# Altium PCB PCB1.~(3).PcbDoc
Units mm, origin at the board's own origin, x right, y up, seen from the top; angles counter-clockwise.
Board outline 48.89 x 49.4 mm, 2 copper layers (Top Layer, Bottom Layer); 29 components, 26 nets, 101 pads, 0 vias.
Unrouted connection lines stored in the file: 55.
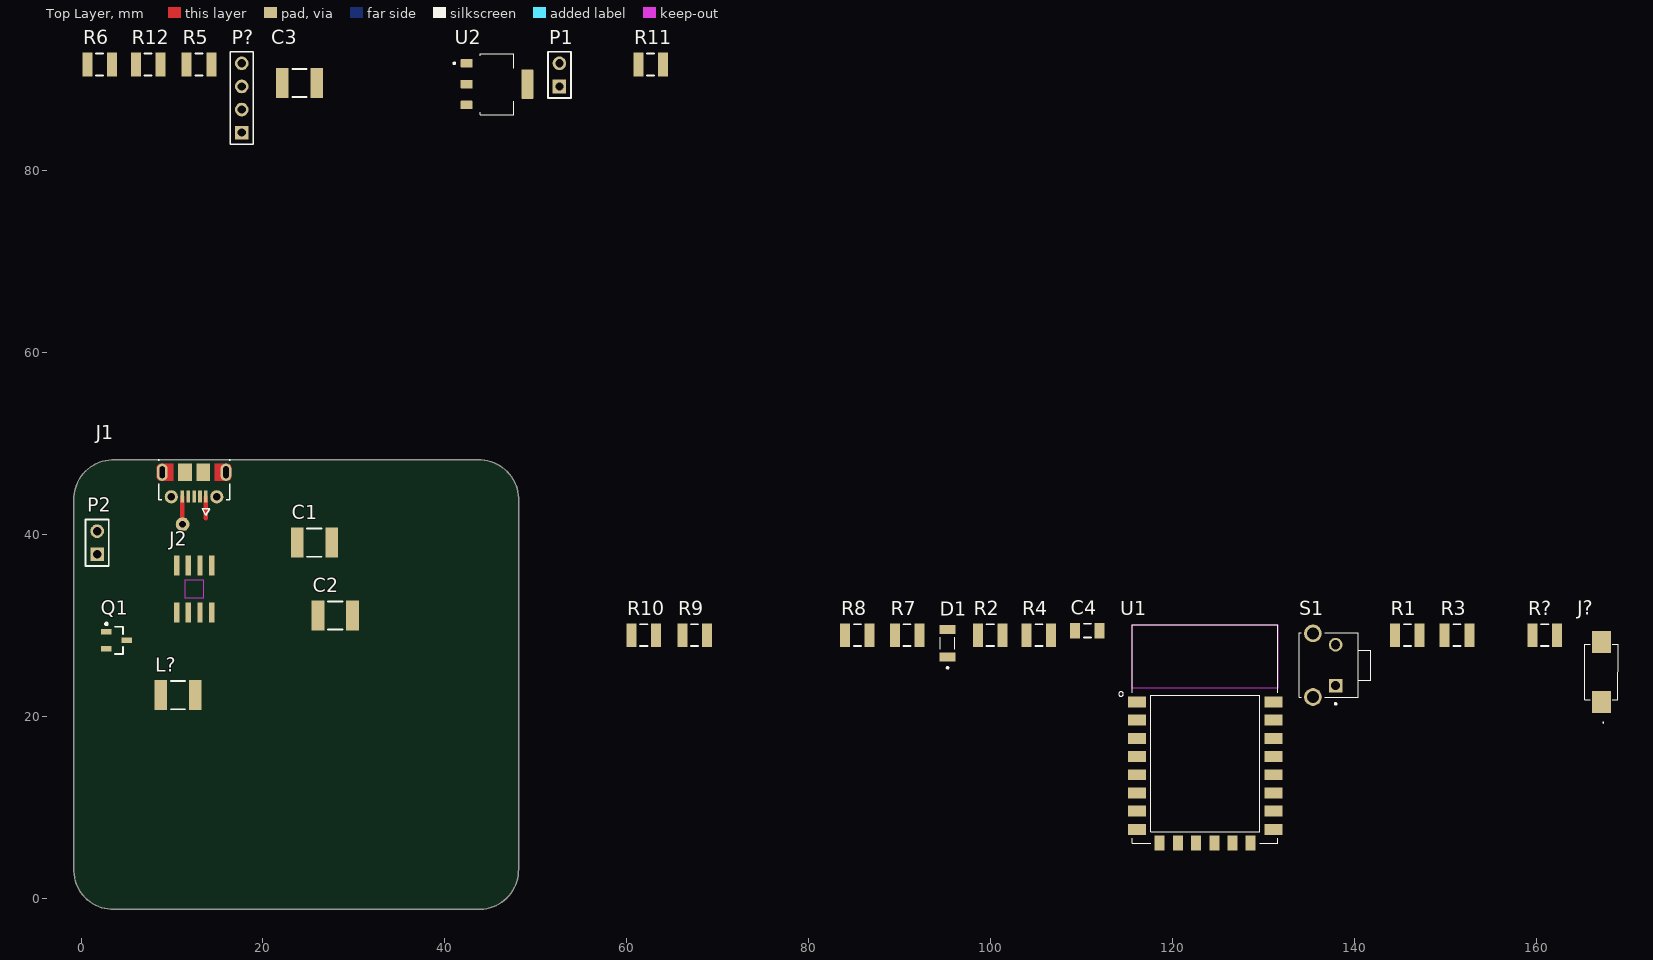
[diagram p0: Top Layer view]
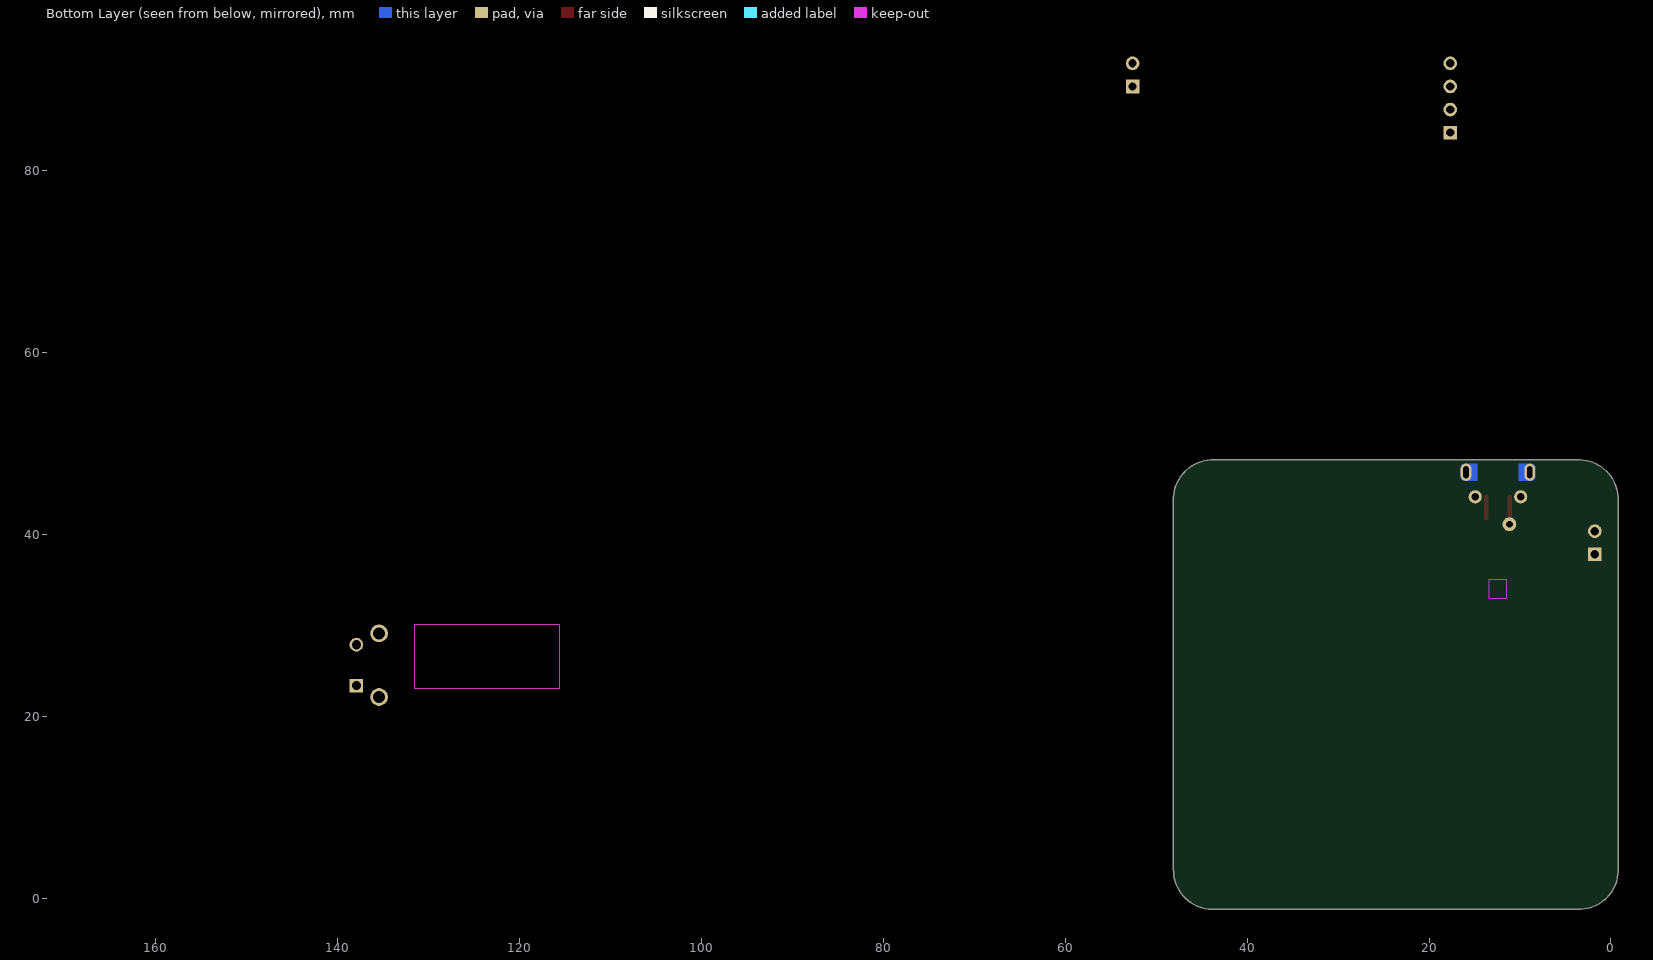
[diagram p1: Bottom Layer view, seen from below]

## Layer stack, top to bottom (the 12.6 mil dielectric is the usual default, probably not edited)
Top Solder: solder mask 0.0102, Solder Resist, Dk 3.5
Top Layer: signal copper 0.0356
Dielectric 1: dielectric 0.32, FR-4, Dk 4.8
Bottom Layer: signal copper 0.0356
Bottom Solder: solder mask 0.0102, Solder Resist, Dk 3.5

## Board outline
-0.794,3.006 -0.794,43.773 cw(c3.524,43.9) 3.397,48.218 43.656,48.218 cw(c43.783,43.9) 48.101,44.027 48.101,3.26 cw(c43.783,3.133) 43.91,-1.185 3.651,-1.185 cw(c3.524,3.133)

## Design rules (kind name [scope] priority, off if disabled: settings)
Clearance [All] p1: gap=0.254 ignorepadtopadclearanceinfootprint=FALSE except(0: Arc-Hole Track-Hole SMDPad-Hole THPad-Hole Via-Hole Fill-Hole Poly-Hole Region-Hole Text-Hole)
PolygonConnect [All] p1: connectstyle=Relief reliefconductorwidth=0.254 reliefentries=4 polygonreliefangle="90 Angle" airgapwidth=0.254
RoomDefinition Sheet1 [InComponentClass('Sheet1')] p1: confinementstyle=ConfineIn formatcopy=TRUE lockcomponents=FALSE outline 154.781,-50.588 347.313,-50.588 347.313,-19.854 154.781,-19.854
RoutingVias [All] p1: holewidth=0.711 width=1.27 viastyle="Through Hole" minholewidth=0.711 minwidth=1.27 maxholewidth=0.711 maxwidth=1.27
SolderMaskExpansion [All] p1: expansion=0.102 istentingtop=FALSE
Width [All] p1: maxlimit=1 minlimit=1 preferedwidth=1 minimp=50.000000 maximp=50.000000 favimp=50.000000
30 further rules are at their usual default settings.

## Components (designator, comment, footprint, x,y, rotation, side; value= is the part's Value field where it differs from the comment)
C1 "" 1812 25.659,39.116 r0 top value=10uF
C2 "" 1812 27.945,31.115 r0 top value=10uF
C3 "" 1812 24.021,89.662 r0 top value=10uF
C4 "" C1206 110.635,29.464 r0 top value=100pF
D1 "LED" LEDC3216X120N 95.268,28.067 r90 top
J1 "1050170001" MOLEX_1050170001 12.43,48.313 r180 top
J2 "L9110" SO-08 12.446,34.036 r0 top
J? "SWITCH" PTS636SM25FSMTRLFS 167.15,24.892 r90 top
L? "Inductor" INDC4532 10.668,22.352 r0 top value=47uH
P1 "Battery" HDR1X2 52.596,89.281 r90 top
P2 "Battery" HDR1X2 1.778,37.846 r90 top
P? "Header 4" HDR1X4 17.671,84.201 r90 top
Q1 "PNP" SOT-23B_N 3.919,28.387 r0 top
R1 "" 14-1210 145.814,28.956 r0 top value=1K
R2 "" 14-1210 99.967,28.956 r0 top value=1K
R3 "" 14-1210 151.275,28.956 r0 top value=1K
R4 "" 14-1210 105.301,28.956 r0 top value=1K
R5 "" 14-1210 12.972,91.694 r0 top value=1K
R6 "" 14-1210 2.05,91.694 r0 top value=1K
R7 "" 14-1210 90.823,28.956 r0 top value=1K
R8 "" 14-1210 85.362,28.956 r0 top value=1K
R9 "" 14-1210 67.455,28.956 r0 top value=1K
R10 "" 14-1210 61.867,28.956 r0 top value=1K
R11 "" 14-1210 62.629,91.694 r0 top value=1K
R12 "" 14-1210 7.384,91.694 r0 top value=1K
R? "" 14-1210 160.927,28.956 r0 top value=1K
S1 "TL1105VF160Q" SW_TL1105VF160Q 137.94,25.654 r90 top
U1 "ESP8266-12E/ESP-12E" XCVR_ESP8266-12E/ESP-12E 123.589,14.605 r0 top
U2 "AMS1117" SOT229P700X180-4N 45.738,89.535 r0 top

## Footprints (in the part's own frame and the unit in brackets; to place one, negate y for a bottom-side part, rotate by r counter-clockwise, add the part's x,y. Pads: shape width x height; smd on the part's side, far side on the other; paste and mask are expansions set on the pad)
14-1210 [mm] "Chip Resistor, Body 3.2x2.5mm, IPC High Density"
  rect 1.1x2.6 smd: 1(-1.35,0) 2(1.35,0)
  silkscreen extent -0.4,-1.2 0.4,1.2, body extent -1.68,-1.32 1.68,1.32, height 0.9
1812 [mm] "Chip Capacitor, Body 4.5x3.2mm, IPC High Density"
  rect 1.4x3.3 smd: 1(-1.9,0) 2(1.9,0)
  silkscreen extent -0.8,-1.55 0.8,1.55, body extent -2.4,-1.7 2.4,1.7, height 1.4
C1206 [mm] "Chip Capacitor, Body 3.2x1.6mm, IPC High Density"
  rect 1.1x1.7 smd: 1(-1.35,0) 2(1.35,0)
  silkscreen extent -0.4,-0.75 0.4,0.75, body extent -1.7,-0.9 1.7,0.9, height 1.3
HDR1X2 [mm] "Connector; Header; 2 Position"
  rect 1.5x1.5 hole 0.9: 1(0,0)
  round 1.5 hole 0.9: 2(2.54,0)
  silkscreen extent -1.27,-1.27 3.81,1.27
HDR1X4 [mm] "Connector; Header; 4 Position"
  rect 1.5x1.5 hole 0.9: 1(0,0)
  round 1.5 hole 0.9: 2(2.54,0) 3(5.08,0) 4(7.62,0)
  silkscreen extent -1.27,-1.27 8.89,1.27
INDC4532 [mm] "Chip Inductor, Body 4.5x3.2mm, IPC High Density"
  rect 1.4x3.3 smd: 1(-1.9,0) 2(1.9,0)
  silkscreen extent -0.8,-1.55 0.8,1.55, body extent -2.4,-1.7 2.4,1.7, height 0.55
LEDC3216X120N [mm]
  rect 1.01x1.73 smd: NEG(1.51,0) POS(-1.51,0)
  silkscreen extent -2.8,-0.8 0.68,0.8, body extent -1.6,-0.8 1.6,0.8, height 1.2
MOLEX_1050170001 [mm]
  rect 0.4x1.35 smd mask+0.064: 1(-1.3,4.125) 2(-0.65,4.125) 3(0,4.125) 4(0.65,4.125) 5(1.3,4.125)
  round 1.45 hole 0.85 mask+0.064: SH1(-2.5,4.15) SH2(2.5,4.15)
  oval 1.2x1.9 hole 0.6 slot 1.3 at 90 deg mask+0: SH3(-3.5,1.45) SH6(3.5,1.45)
  rect 1.5x1.9 smd mask+0.064: SH4(-1,1.45) SH5(1,1.45)
  Top Layer region: -2.3,0.5 -3.6,0.5 -3.626,0.501 -3.652,0.503 -3.678,0.506 -3.704,0.511 -3.729,0.517 -3.755,0.524 -3.779,0.533 -3.803,0.543 -3.827,0.554 -3.85,0.567 -3.872,0.581 -3.894,0.595 -3.915,0.611 -3.935,0.628 -3.954,0.646 -3.972,0.665 -3.989,0.685 -4.005,0.706 -4.019,0.728 -4.033,0.75 -4.046,0.773 -4.057,0.797 -4.067,0.821 -4.076,0.845 -4.083,0.871 -4.089,0.896 -4.094,0.922 -4.097,0.948 -4.099,0.974 -4.1,1 -4.1,1.9 -4.099,1.926 -4.097,1.952 -4.094,1.978 -4.089,2.004 -4.083,2.029 -4.076,2.055 -4.067,2.079 -4.057,2.103 -4.046,2.127 -4.033,2.15 -4.019,2.172 -4.005,2.194 -3.989,2.215 -3.972,2.235 -3.954,2.254 -3.935,2.272 -3.915,2.289 -3.894,2.305 -3.872,2.319 -3.85,2.333 -3.827,2.346 -3.803,2.357 -3.779,2.367 -3.755,2.376 -3.729,2.383 -3.704,2.389 -3.678,2.394 -3.652,2.397 -3.626,2.399 -3.6,2.4 -2.3,2.4
  Top Layer region: 3.626,2.399 3.652,2.397 3.678,2.394 3.704,2.389 3.729,2.383 3.755,2.376 3.779,2.367 3.803,2.357 3.827,2.346 3.85,2.333 3.872,2.319 3.894,2.305 3.915,2.289 3.935,2.272 3.954,2.254 3.972,2.235 3.989,2.215 4.005,2.194 4.019,2.172 4.033,2.15 4.046,2.127 4.057,2.103 4.067,2.079 4.076,2.055 4.083,2.029 4.089,2.004 4.094,1.978 4.097,1.952 4.099,1.926 4.1,1.9 4.1,1 4.099,0.974 4.097,0.948 4.094,0.922 4.089,0.896 4.083,0.871 4.076,0.845 4.067,0.821 4.057,0.797 4.046,0.773 4.033,0.75 4.019,0.728 4.005,0.706 3.989,0.685 3.972,0.665 3.954,0.646 3.935,0.628 3.915,0.611 3.894,0.595 3.872,0.581 3.85,0.567 3.827,0.554 3.803,0.543 3.779,0.533 3.755,0.524 3.729,0.517 3.704,0.511 3.678,0.506 3.652,0.503 3.626,0.501 3.6,0.5 2.3,0.5 2.3,2.4 3.6,2.4
  Bottom Layer region: 3.626,2.399 3.652,2.397 3.678,2.394 3.704,2.389 3.729,2.383 3.755,2.376 3.779,2.367 3.803,2.357 3.827,2.346 3.85,2.333 3.872,2.319 3.894,2.305 3.915,2.289 3.935,2.272 3.954,2.254 3.972,2.235 3.989,2.215 4.005,2.194 4.019,2.172 4.033,2.15 4.046,2.127 4.057,2.103 4.067,2.079 4.076,2.055 4.083,2.029 4.089,2.004 4.094,1.978 4.097,1.952 4.099,1.926 4.1,1.9 4.1,1 4.099,0.974 4.097,0.948 4.094,0.922 4.089,0.896 4.083,0.871 4.076,0.845 4.067,0.821 4.057,0.797 4.046,0.773 4.033,0.75 4.019,0.728 4.005,0.706 3.989,0.685 3.972,0.665 3.954,0.646 3.935,0.628 3.915,0.611 3.894,0.595 3.872,0.581 3.85,0.567 3.827,0.554 3.803,0.543 3.779,0.533 3.755,0.524 3.729,0.517 3.704,0.511 3.678,0.506 3.652,0.503 3.626,0.501 3.6,0.5 2.3,0.5 2.3,2.4 3.6,2.4
  Bottom Layer region: -2.3,0.5 -3.6,0.5 -3.626,0.501 -3.652,0.503 -3.678,0.506 -3.704,0.511 -3.729,0.517 -3.755,0.524 -3.779,0.533 -3.803,0.543 -3.827,0.554 -3.85,0.567 -3.872,0.581 -3.894,0.595 -3.915,0.611 -3.935,0.628 -3.954,0.646 -3.972,0.665 -3.989,0.685 -4.005,0.706 -4.019,0.728 -4.033,0.75 -4.046,0.773 -4.057,0.797 -4.067,0.821 -4.076,0.845 -4.083,0.871 -4.089,0.896 -4.094,0.922 -4.097,0.948 -4.099,0.974 -4.1,1 -4.1,1.9 -4.099,1.926 -4.097,1.952 -4.094,1.978 -4.089,2.004 -4.083,2.029 -4.076,2.055 -4.067,2.079 -4.057,2.103 -4.046,2.127 -4.033,2.15 -4.019,2.172 -4.005,2.194 -3.989,2.215 -3.972,2.235 -3.954,2.254 -3.935,2.272 -3.915,2.289 -3.894,2.305 -3.872,2.319 -3.85,2.333 -3.827,2.346 -3.803,2.357 -3.779,2.367 -3.755,2.376 -3.729,2.383 -3.704,2.389 -3.678,2.394 -3.652,2.397 -3.626,2.399 -3.6,2.4 -2.3,2.4
  silkscreen extent -3.9,0 3.9,6.15
PTS636SM25FSMTRLFS [mm]
  rect 2.4x2.1 smd: 1(-3.3,0) 2(3.3,0)
  silkscreen extent -5.6,-1.85 3.05,1.85, body extent -4.29,-2.8 4.29,0, height 1.85
SO-08 [mm]
  rect 0.6x2.2 smd: 1(-1.905,-2.6) 2(-0.635,-2.6) 3(0.635,-2.6) 4(1.905,-2.6) 5(1.905,2.6) 6(0.635,2.6) 7(-0.635,2.6) 8(-1.905,2.6)
  Keep-Out Layer region: 1,-1 -1,-1 -1,1 1,1
SOT229P700X180-4N [mm]
  rrect15% 1.31x0.93 smd: 1(-3.345,2.29) 2(-3.345,0) 3(-3.345,-2.29)
  rrect15% 1.31x3.24 smd: 4(3.345,0)
  silkscreen extent -4.8,-3.36 1.86,3.36, body extent -3.25,-3.5 3.25,3.5, height 1.8
SOT-23B_N [mm] "SOT23, 3-Leads, Body 2.9x1.3mm, Pitch 0.95mm, Lead Span 2.4mm, IPC Medium Density"
  rect 1.15x0.6 smd: 1(-1.125,0.95) 2(-1.125,-0.95) 3(1.125,0)
  silkscreen extent -1.25,-1.5 0.7,1.92, body extent -0.7,-1.5 0.7,1.5, height 1.14
SW_TL1105VF160Q [mm]
  rect 1.508x1.508 / inner round 1.508 / far side rect 1.508x1.508 hole 1 mask+0.102: 1(-2.25,0)
  round 1.508 hole 1 mask+0.102: 2(2.25,0)
  round 1.95 hole 1.3 mask+0.102: S1(-3.5,2.5) S2(3.5,2.5)
  silkscreen extent -4.35,-3.85 3.55,4, body extent -7.7,-4.64 3.3,3.21, height 4.2
XCVR_ESP8266-12E/ESP-12E [mm]
  rect 2x1.2 smd: 1(-7.5,7) 2(-7.5,5) 3(-7.5,3) 4(-7.5,1) 5(-7.5,-1) 6(-7.5,-3) 7(-7.5,-5) 8(-7.5,-7) 15(7.5,-7) 16(7.5,-5) 17(7.5,-3) 18(7.5,-1) 19(7.5,1) 20(7.5,3) 21(7.5,5) 22(7.5,7)
  rect 1.1x1.7 smd: 9(-5,-8.5) 10(-3,-8.5) 11(-1,-8.5) 12(1,-8.5) 13(3,-8.5) 14(5,-8.5)
  Keep-Out Layer region: 8,8.51 -8.009,8.51 -8.009,15.5 8,15.5
  Keep-Out Layer region: 8,8.51 -8.009,8.51 -8.009,15.5 8,15.5
  silkscreen extent -9.5,-8.5 8,15.5, body extent -8,-12 8,12, height 3

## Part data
C1 C2 C3: library part "Cap Pol3", "Polarized Capacitor (Surface Mount)"
C4: library part "Cap Semi", "Capacitor (Semiconductor SIM Model)"
D1: library part LHN974_RED_LED_1206, "2.6 V Red LED SMD", Package=None
J1: "USB - micro B USB 2.0 Receptacle Connector 5 Position Surface Mount, Right Angle; Through Hole", Package=None
J2: "Motor control driver chip", Package=Package
J?: library part PTS636_SM25F_SMTR_LFS, "Tactile Switch SPST-NO Top Actuated Surface Mount", Package=None
P1 P2: library part "Header 2", "Header, 2-Pin"
P?: "Header, 4-Pin"
Q1: "PNP Bipolar Transistor"
R1 R2 R3 R4 R5 R6 R7 R8 R9 R10 R11 R12 R?: library part Res3, "Resistor"
S1: "Tactile Switch, TL1105 Series, SPST-NO, 3.85mm Side Actuated, 0.05A, 12VDC, PC", Package=None
U1: "This WiFi module has a 32-bit MCU micro and clock speeds supporting 80 MHz or 160 MHz. Supports the RTOS and integrated Wi-Fi MAC/BB/RF/PA/LNA, and has an on-board antenna.", Package=None
U2: "1A LOW DROPOUT VOLTAGE REGULATOR SOT-223", Package="SOT-223 Seeed Technology"

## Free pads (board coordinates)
  round 1.524 hole 0.762: 2(11.176,41.148)

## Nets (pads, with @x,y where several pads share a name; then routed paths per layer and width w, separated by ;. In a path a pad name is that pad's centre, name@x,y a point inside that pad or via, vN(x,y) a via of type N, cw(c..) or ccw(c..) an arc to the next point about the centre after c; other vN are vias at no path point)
+3.3: C3.1 P?.4 R9.2 R10.2 R11.2 R12.1 S1.1 U1.8 U2.2 U2.4
+5: J1.1 U2.3 | length 2.4
  Top Layer w0.5: 13.73,41.797 J1.1
ADC: R3.1 R4.1 U1.2
Battery: P2.1 Q1.3 R4.2
EN: R9.1 U1.3
GND: C1.2 C2.2 C3.2 C4.1 D1.NEG J1.5 J2.7 J2.8 J?.2 P2.2 P?.1 pad.2 R3.2 R8.2 U1.15 U2.1 | length 2.2
  Top Layer w0.5: 11.13,41.956 J1.5
GPIO0: R11.1 U1.18
GPIO2: R10.1 U1.17
GPIO4: R7.1 U1.19
GPIO5: R2.2 U1.20
GPIO13: P?.3 R12.2 U1.7
GPIO14: R5.2 U1.5
GPIO15: R8.1 U1.16
GPIO16: R6.2 U1.4
L1: J2.1 R5.1
L2: J2.2 R6.1
NetC1_1: C1.1 J2.3 L?.1 Q1.1
NetC2_1: C2.1 J2.6 L?.2
NetD1_POS: D1.POS R7.2
NetJ2_4: J2.4 J2.5
NetJ?_1: J?.1 R?.2
NetR1_1: R1.1 R2.1 S1.2
ON/OFF: Q1.2 R1.2
RESET: C4.2 R?.1 U1.1
RX: P1.2 U1.21
TX: P1.1 U1.22
pads on no net: J1.2 J1.3 J1.4 J1.SH1 J1.SH2 J1.SH3 J1.SH4 J1.SH5 J1.SH6 P?.2 S1.S1 S1.S2 U1.6 U1.9 U1.10 U1.11 U1.12 U1.13 U1.14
